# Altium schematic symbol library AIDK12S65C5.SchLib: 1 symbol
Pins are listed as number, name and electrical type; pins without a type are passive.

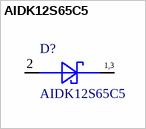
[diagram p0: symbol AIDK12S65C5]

## AIDK12S65C5
designator D?
Schottky Diode Symbol 3 Pins, 1 Cathode , 2 Anode, 3 Cathode; Manufacturer: Infineon Technologies; PacakageReferene: PG-TO263-2-1
pins: 1 Cathode, 2 Anode, 3 Cathode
